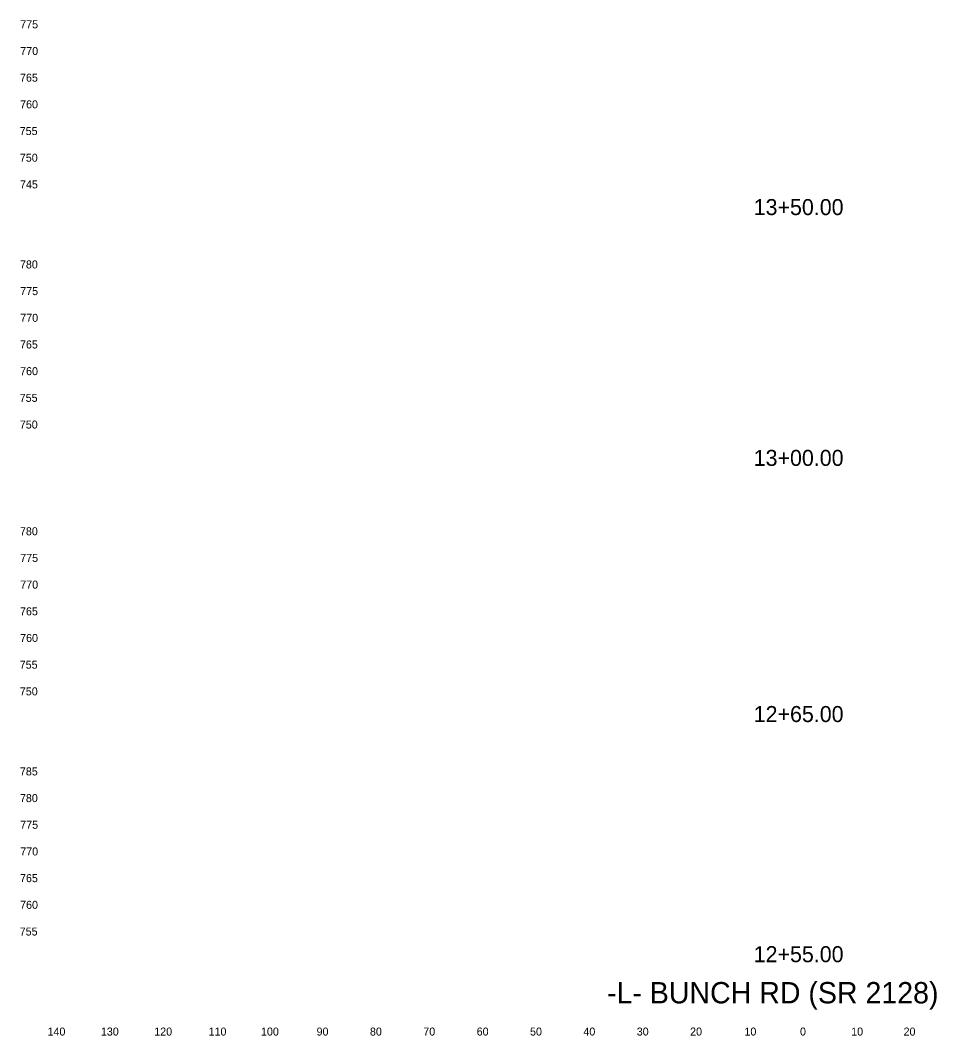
# Model space of a CAD drawing. Extents: x 2473106 to 2475402, y 633617 to 633851.
# Drawn here: x 2473509 to 2473680.8, y 633618.8 to 633809.1 of the extents above; entities that cross this region are included whole.
import ezdxf

# ---------------------------------------------------------------- set-up
doc = ezdxf.new("R2010")
doc.units = 0
for name, color, linetype in [('Exist Cross Section Cell', 7, 'Continuous'), ('Exist XS Center Line Elevation Label', 7, 'Continuous'), ('Exist XS Ground Line', 7, 'Continuous'), ('Scratch_Level_5', 7, 'Continuous')]:
    doc.layers.add(name, color=color, linetype=linetype)

msp = doc.modelspace()

# ---------------------------------------------------------------- texts
at = {"layer": 'Exist Cross Section Cell'}
for s, p in [('140', (2473514.13, 633618.82)), ('130', (2473524.13, 633618.82)), ('120', (2473534.13, 633618.82)), ('110', (2473544.31, 633618.82)), ('100', (2473554.13, 633618.82)), ('90', (2473564.55, 633618.82)), ('80', (2473574.55, 633618.82)), ('70', (2473584.55, 633618.82)), ('60', (2473594.55, 633618.82)), ('50', (2473604.55, 633618.82)), ('40', (2473614.55, 633618.82)), ('30', (2473624.55, 633618.82)), ('20', (2473634.55, 633618.82)), ('10', (2473644.73, 633618.82)), ('0', (2473655.14, 633618.82)), ('0', (2473655.14, 633618.82)), ('10', (2473664.73, 633618.82)), ('20', (2473674.55, 633618.82))]:
    msp.add_text(s, height=1.5, dxfattribs=at).set_placement(p)
at = {"layer": 'Exist XS Center Line Elevation Label'}
for s, p in [('13+50.00', (2473646.46, 633772.57)), ('13+00.00', (2473646.46, 633725.57)), ('12+65.00', (2473646.46, 633677.57)), ('12+55.00', (2473646.46, 633632.57))]:
    msp.add_text(s, height=3, dxfattribs=at).set_placement(p)
at = {"layer": 'Exist XS Ground Line'}
for s, p in [('775', (2473509.01, 633807.57)), ('770', (2473509.02, 633802.57)), ('765', (2473508.97, 633797.57)), ('760', (2473508.99, 633792.57)), ('755', (2473508.92, 633787.57)), ('750', (2473508.94, 633782.57)), ('745', (2473508.97, 633777.57)), ('780', (2473508.96, 633762.57)), ('775', (2473509.01, 633757.57)), ('770', (2473509.02, 633752.57)), ('765', (2473508.97, 633747.57)), ('760', (2473508.99, 633742.57)), ('755', (2473508.92, 633737.57)), ('750', (2473508.94, 633732.57)), ('780', (2473508.96, 633712.57)), ('775', (2473509.01, 633707.57)), ('770', (2473509.02, 633702.57)), ('765', (2473508.97, 633697.57)), ('760', (2473508.99, 633692.57)), ('755', (2473508.92, 633687.57)), ('750', (2473508.94, 633682.57)), ('785', (2473508.95, 633667.57)), ('780', (2473508.96, 633662.57)), ('775', (2473509.01, 633657.57)), ('770', (2473509.02, 633652.57)), ('765', (2473508.97, 633647.57)), ('760', (2473508.99, 633642.57)), ('755', (2473508.92, 633637.57))]:
    msp.add_text(s, height=1.5, dxfattribs=at).set_placement(p)
at = {"layer": 'Scratch_Level_5'}
msp.add_text('-L- BUNCH RD (SR 2128)', height=4, dxfattribs=at).set_placement((2473618.97, 633624.85))

doc.saveas('drawing.dxf')
